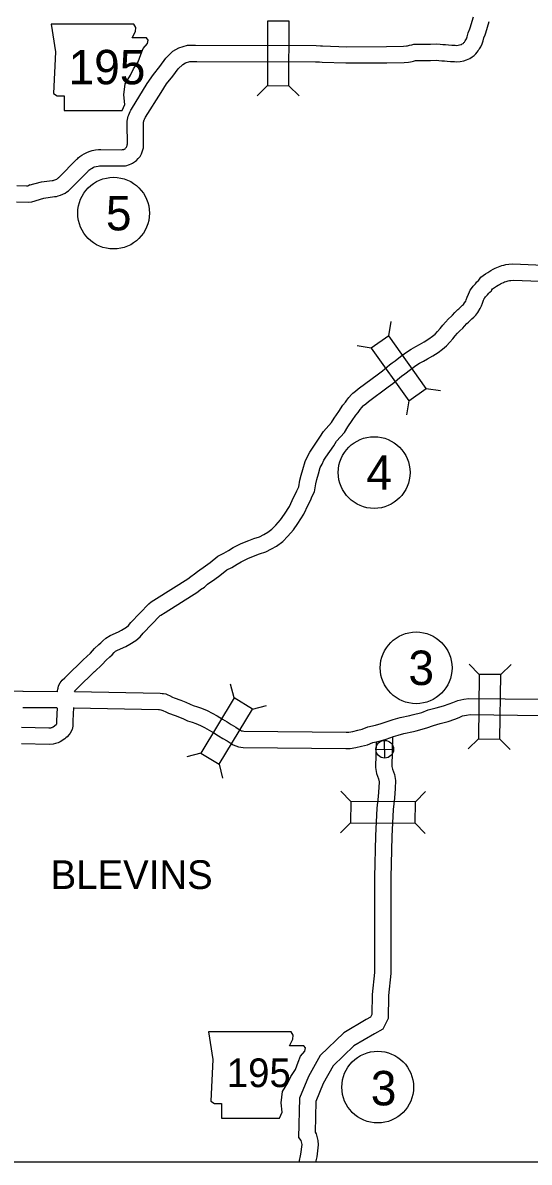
# Model space of a CAD drawing. Extents: x 79818 to 83933, y 50884 to 53307.
# Drawn here: x 81175.4 to 81299.7, y 52610.7 to 52890.4 of the extents above; entities that cross this region are included whole.
import ezdxf

# ---------------------------------------------------------------- set-up
doc = ezdxf.new("R2010")
doc.units = 0
for name, color, linetype in [('Level 10', 7, 'Continuous'), ('Level 12', 7, 'Continuous'), ('Level 15', 7, 'Continuous'), ('Level 20', 7, 'Continuous'), ('Level 21', 7, 'Continuous'), ('Level 26', 7, 'Continuous'), ('Level 27', 7, 'Continuous'), ('Level 6', 7, 'Continuous'), ('R_No Plot', 7, 'Continuous')]:
    doc.layers.add(name, color=color, linetype=linetype)

msp = doc.modelspace()

# ---------------------------------------------------------------- linework, layer by layer
at = {"layer": 'Level 10'}
for points in [[(81281, 52880.86), (81281.3, 52880.84), (81281.88, 52880.81), (81282.75, 52880.85), (81283.63, 52881.06), (81284.24, 52881.25), (81284.65, 52881.42), (81285.1, 52881.63), (81285.68, 52881.97), (81286.19, 52882.37), (81286.57, 52882.75), (81286.91, 52883.13), (81287.16, 52883.49), (81287.33, 52883.79), (81287.46, 52883.97), (81287.75, 52884.45), (81288.13, 52885.16), (81288.34, 52885.97), (81288.51, 52886.64), (81288.83, 52887.41), (81289, 52887.87), (81289.84, 52890.64)], [(81281.22, 52884.85), (81281.52, 52884.83), (81281.88, 52884.81), (81282.19, 52884.83), (81282.59, 52884.92), (81282.86, 52885.01), (81283.01, 52885.07), (81283.25, 52885.19), (81283.43, 52885.28), (81283.52, 52885.36), (81283.65, 52885.49), (81283.77, 52885.62), (81283.78, 52885.64), (81283.93, 52885.91), (81284.1, 52886.15), (81284.29, 52886.45), (81284.38, 52886.63), (81284.46, 52886.94), (81284.7, 52887.91), (81285.11, 52888.88), (81285.21, 52889.14), (81286.02, 52891.82)], [(81202.08, 52869.16), (81205.97, 52875.43), (81207.47, 52877.7), (81209.04, 52879.66), (81210.5, 52881.64), (81212.23, 52883.38), (81213.73, 52884.22), (81215.8, 52884.86), (81217.76, 52884.9)], [(81205.56, 52867.19), (81209.36, 52873.29), (81210.71, 52875.35), (81212.21, 52877.23), (81213.54, 52879.03), (81214.67, 52880.16), (81215.32, 52880.53), (81216.43, 52880.87), (81218.13, 52880.9)], [(81201.08, 52860.53), (81201.05, 52865.56), (81201.05, 52865.85), (81201.07, 52866.2), (81201.12, 52866.61), (81201.21, 52867.05), (81201.3, 52867.43), (81201.42, 52867.81), (81201.57, 52868.2), (81201.74, 52868.57), (81201.95, 52868.95), (81202.08, 52869.16)], [(81205.08, 52860.56), (81205.05, 52865.54), (81205.05, 52865.68), (81205.06, 52865.83), (81205.08, 52865.99), (81205.11, 52866.19), (81205.15, 52866.34), (81205.2, 52866.49), (81205.26, 52866.65), (81205.31, 52866.76), (81205.43, 52866.98), (81205.56, 52867.19)], [(81188.65, 52856.82), (81188.83, 52856.99), (81189.05, 52857.19), (81189.45, 52857.53), (81189.89, 52857.84), (81190.48, 52858.21), (81191.13, 52858.53), (81191.7, 52858.76), (81192.42, 52858.99), (81193.26, 52859.17), (81194, 52859.25), (81194.59, 52859.26), (81199.7, 52859.22), (81199.92, 52859.23), (81199.99, 52859.24), (81200.04, 52859.25), (81200.18, 52859.28), (81200.21, 52859.29), (81200.33, 52859.34), (81200.38, 52859.37), (81200.53, 52859.46), (81200.65, 52859.56), (81200.74, 52859.66), (81200.86, 52859.81), (81200.94, 52859.96), (81200.99, 52860.07), (81201.04, 52860.22), (81201.06, 52860.32), (81201.07, 52860.42), (81201.08, 52860.62)], [(81191.44, 52853.96), (81191.57, 52854.08), (81191.67, 52854.17), (81191.9, 52854.36), (81192.11, 52854.51), (81192.43, 52854.71), (81192.78, 52854.89), (81193.06, 52855), (81193.44, 52855.12), (81193.89, 52855.21), (81194.28, 52855.25), (81194.63, 52855.26), (81199.77, 52855.22), (81200.27, 52855.24), (81200.63, 52855.29), (81200.95, 52855.35), (81201.35, 52855.46), (81201.63, 52855.55), (81202, 52855.71), (81202.35, 52855.88), (81202.86, 52856.2), (81203.35, 52856.6), (81203.77, 52857.03), (81204.19, 52857.58), (81204.52, 52858.16), (81204.75, 52858.68), (81204.91, 52859.21), (81205.01, 52859.67), (81205.06, 52860.1), (81205.08, 52860.47)], [(81180.05, 52851.31), (81182.67, 52851.64), (81182.89, 52851.68), (81183.06, 52851.72), (81183.31, 52851.8), (81183.55, 52851.9), (81183.76, 52852.01), (81183.94, 52852.13), (81184.1, 52852.25), (81184.23, 52852.36), (81184.33, 52852.46), (81188.63, 52856.79)], [(81176.37, 52850.34), (81176.65, 52850.36), (81176.94, 52850.5), (81180.05, 52851.31)], [(81180.57, 52847.34), (81183.25, 52847.69), (81183.67, 52847.75), (81184.12, 52847.86), (81184.7, 52848.04), (81185.27, 52848.28), (81185.79, 52848.56), (81186.24, 52848.85), (81186.61, 52849.14), (81186.92, 52849.4), (81187.14, 52849.61), (81191.47, 52853.98)], [(81173.98, 52850.39), (81176.37, 52850.35)], [(81176.37, 52850.34), (81176.65, 52850.36), (81176.94, 52850.5), (81177.21, 52850.64)], [(81173.9, 52846.39), (81176.72, 52846.34)], [(81176.72, 52846.35), (81177.62, 52846.43), (81180.57, 52847.34)], [(81183.83, 52722.25), (81183.69, 52719.01), (81183.72, 52718.43), (81183.7, 52718.23), (81183.6, 52718.06), (81183.33, 52717.82), (81183.17, 52717.72), (81182.86, 52717.51), (81182.62, 52717.37), (81182.56, 52717.33), (81182.39, 52717.28), (81182.26, 52717.25), (81181.86, 52717.23), (81175.13, 52717.37)], [(81187.84, 52722.34), (81187.69, 52719.02), (81187.73, 52718.38), (81187.68, 52717.76), (81187.57, 52716.89), (81187.03, 52716), (81186.84, 52715.67), (81186.35, 52715.08), (81185.98, 52714.82), (81185.71, 52714.58), (81185.37, 52714.38), (81185.03, 52714.14), (81184.56, 52713.87), (81184.07, 52713.6), (81183.46, 52713.43), (81182.88, 52713.27), (81181.92, 52713.23), (81175.15, 52713.37)], [(81266.12, 52715.07), (81265.99, 52707.81), (81266.09, 52707.17), (81266.59, 52705.88), (81266.85, 52704.35), (81266.77, 52702.39), (81266.58, 52700.04), (81266.28, 52697.3), (81265.95, 52690.62), (81265.69, 52680.6), (81265.72, 52657.03), (81265.16, 52651.64), (81265.06, 52645.98), (81263.76, 52643.37), (81261.68, 52642.22), (81256.62, 52639.23), (81251.54, 52634.39), (81249.11, 52630.03), (81247.3, 52625.59), (81247.13, 52618.03), (81247.37, 52617.7), (81247.77, 52616.03), (81247.87, 52614.97), (81247.53, 52612.04), (81247.24, 52610.7)], [(81262.1, 52713.9), (81261.99, 52707.54), (81262.21, 52706.13), (81262.71, 52704.82), (81262.84, 52704.09), (81262.78, 52702.63), (81262.6, 52700.42), (81262.29, 52697.62), (81261.96, 52690.77), (81261.69, 52680.65), (81261.72, 52657.24), (81261.16, 52651.88), (81261.08, 52646.96), (81260.74, 52646.27), (81259.69, 52645.69), (81254.19, 52642.44), (81248.34, 52636.87), (81245.49, 52631.77), (81243.32, 52626.42), (81243.1, 52616.78), (81243.66, 52615.99), (81243.81, 52615.37), (81243.85, 52615.01), (81243.58, 52612.69), (81243.15, 52610.7)]]:
    msp.add_lwpolyline(points, dxfattribs=at)
at = {"layer": 'Level 12'}
for points in [[(81217.76, 52884.9), (81247.4, 52884.81), (81248.5, 52884.73), (81248.96, 52884.69), (81254.94, 52884.5), (81264.63, 52884.52)], [(81264.63, 52884.52), (81268.81, 52884.64), (81269.59, 52884.7), (81269.79, 52884.73), (81270.05, 52884.79), (81270.32, 52884.86), (81270.88, 52884.99), (81271.32, 52885.08), (81272.16, 52885.14), (81273.02, 52885.14), (81273.69, 52885.14), (81274.31, 52885.14), (81275.47, 52885.12), (81277.01, 52885.16), (81277.82, 52885.1), (81278.48, 52885.04), (81279.12, 52885.01), (81279.87, 52884.96), (81280.68, 52884.88), (81281.22, 52884.85)], [(81218.13, 52880.9), (81247.24, 52880.81), (81248.2, 52880.74), (81248.86, 52880.69), (81254.66, 52880.5), (81264.75, 52880.52)], [(81264.75, 52880.52), (81269.02, 52880.64), (81270.08, 52880.73), (81270.52, 52880.8), (81270.95, 52880.89), (81271.3, 52880.98), (81271.75, 52881.09), (81271.85, 52881.11), (81272.3, 52881.14), (81273.04, 52881.14), (81273.7, 52881.14), (81274.28, 52881.14), (81275.48, 52881.12), (81276.91, 52881.15), (81277.49, 52881.11), (81278.22, 52881.04), (81278.9, 52881.02), (81279.53, 52880.97), (81280.38, 52880.89), (81281, 52880.86)]]:
    msp.add_lwpolyline(points, dxfattribs=at)
at = {"layer": 'Level 15'}
for points in [[(81287.11, 52826.94), (81287.81, 52827.94), (81288.95, 52828.74), (81289.48, 52829.06), (81289.79, 52829.27), (81290.28, 52829.59), (81290.8, 52829.87), (81291.29, 52830.11), (81291.7, 52830.28), (81292.15, 52830.5), (81292.98, 52830.75), (81293.44, 52830.86), (81293.92, 52831), (81294.67, 52831.12), (81295.65, 52831.2), (81308.86, 52830.66)], [(81190.28, 52734), (81192.05, 52735.67), (81193.06, 52736.77), (81194.1, 52737.75), (81194.58, 52738.16), (81195.04, 52738.64), (81195.77, 52739.35), (81196.83, 52739.96), (81198.89, 52740.88), (81199.63, 52741.3), (81200.84, 52742.05), (81201.36, 52742.47), (81201.91, 52743.2), (81206.38, 52747.74), (81206.9, 52748.21), (81208.23, 52749.03), (81215.94, 52753.88), (81216.64, 52754.49), (81217.58, 52755.08), (81218.28, 52755.7), (81220.24, 52757.1), (81221.4, 52757.91), (81223.29, 52759.41), (81224.71, 52760.18), (81225.9, 52760.87), (81227.02, 52761.59), (81229.01, 52762.52), (81230.87, 52763.27), (81232.12, 52763.81), (81233.51, 52764.23), (81234.55, 52764.76), (81235.52, 52765.3), (81236.56, 52766.08), (81237.53, 52767.06), (81238.64, 52768.37), (81239.63, 52769.76), (81240.86, 52771.63), (81241.82, 52773.85), (81242.45, 52774.94), (81242.65, 52775.52), (81243.11, 52776.47), (81243.37, 52778.09), (81243.75, 52779.34), (81244.11, 52780.69), (81244.66, 52782.69), (81245.26, 52783.87), (81245.82, 52784.98), (81246.46, 52785.96), (81247.5, 52787.43), (81248.33, 52788.67), (81249.19, 52790.07), (81251.12, 52792.24), (81251.83, 52793.35), (81252.92, 52794.99), (81253.95, 52796.52), (81254.59, 52797.26), (81254.95, 52797.75), (81255.42, 52798.43), (81256.03, 52799.12), (81256.42, 52799.48), (81257.03, 52799.93), (81257.67, 52800.52), (81262.65, 52804.18), (81263.69, 52804.97), (81265.38, 52806.4), (81266.07, 52806.87), (81266.76, 52807.37), (81268.08, 52808.42), (81269.58, 52809.55), (81270.72, 52810.26), (81271.81, 52810.87), (81272.78, 52811.36), (81273.93, 52812.04), (81275.07, 52812.79), (81275.97, 52813.41), (81276.61, 52813.96), (81277.16, 52814.56), (81277.79, 52815.34), (81278.45, 52816.14), (81279.13, 52816.91), (81279.9, 52817.68), (81280.62, 52818.35), (81280.85, 52818.56), (81281.42, 52819.28), (81282.15, 52819.99), (81282.38, 52820.16), (81282.85, 52820.63), (81283.3, 52821.02), (81283.51, 52821.24), (81283.8, 52821.6), (81284.08, 52822.05), (81284.2, 52822.34), (81284.43, 52822.98), (81284.73, 52823.78), (81284.98, 52824.32), (81285.17, 52824.72), (81285.48, 52825.18), (81285.88, 52825.73), (81286.45, 52826.31), (81286.85, 52826.77), (81287.08, 52826.98)], [(81290.37, 52824.63), (81290.68, 52825.06), (81291.15, 52825.39), (81291.63, 52825.69), (81292.01, 52825.94), (81292.33, 52826.15), (81292.63, 52826.31), (81292.94, 52826.47), (81293.33, 52826.62), (81293.61, 52826.76), (81294.03, 52826.89), (81294.48, 52827), (81294.8, 52827.09), (81295.15, 52827.14), (81295.74, 52827.2), (81308.77, 52826.66)], [(81193.02, 52731.09), (81194.9, 52732.86), (81195.91, 52733.96), (81196.76, 52734.77), (81197.33, 52735.24), (81197.88, 52735.83), (81198.2, 52736.13), (81198.64, 52736.39), (81200.69, 52737.31), (81201.66, 52737.85), (81203.15, 52738.78), (81204.26, 52739.67), (81204.94, 52740.58), (81209.16, 52744.86), (81209.32, 52745), (81210.34, 52745.63), (81218.35, 52750.66), (81219.04, 52751.28), (81219.97, 52751.86), (81220.77, 52752.56), (81222.55, 52753.83), (81223.8, 52754.7), (81225.5, 52756.06), (81226.67, 52756.69), (81227.99, 52757.46), (81228.96, 52758.08), (81230.6, 52758.85), (81232.4, 52759.58), (81233.5, 52760.05), (81235.02, 52760.51), (81236.42, 52761.23), (81237.7, 52761.93), (81239.2, 52763.07), (81240.48, 52764.36), (81241.8, 52765.91), (81242.93, 52767.49), (81244.39, 52769.72), (81245.4, 52772.04), (81246.1, 52773.26), (81246.36, 52773.99), (81246.97, 52775.26), (81247.28, 52777.19), (81247.6, 52778.25), (81247.97, 52779.65), (81248.41, 52781.23), (81248.83, 52782.06), (81249.29, 52782.98), (81249.77, 52783.71), (81250.79, 52785.16), (81251.7, 52786.51), (81252.42, 52787.68), (81254.32, 52789.82), (81255.18, 52791.17), (81256.24, 52792.77), (81257.13, 52794.09), (81257.71, 52794.75), (81258.2, 52795.41), (81258.58, 52795.96), (81258.91, 52796.34), (81258.98, 52796.4), (81259.57, 52796.83), (81260.21, 52797.42), (81265.04, 52800.98), (81266.19, 52801.84), (81267.82, 52803.22), (81268.37, 52803.6), (81269.17, 52804.18), (81270.53, 52805.26), (81271.84, 52806.25), (81272.75, 52806.81), (81273.69, 52807.33), (81274.71, 52807.86), (81276.04, 52808.64), (81277.31, 52809.47), (81278.41, 52810.24), (81279.4, 52811.08), (81280.19, 52811.95), (81280.89, 52812.81), (81281.5, 52813.55), (81282.05, 52814.17), (81282.67, 52814.79), (81283.36, 52815.44), (81283.81, 52815.86), (81284.39, 52816.59), (81284.73, 52816.92), (81284.98, 52817.1), (81285.57, 52817.7), (81286.09, 52818.14), (81286.55, 52818.64), (81287.07, 52819.29), (81287.64, 52820.21), (81287.93, 52820.89), (81288.18, 52821.58), (81288.43, 52822.25), (81288.59, 52822.62), (81288.64, 52822.7), (81288.76, 52822.89), (81288.94, 52823.14), (81289.39, 52823.6), (81289.72, 52823.97), (81290.09, 52824.31)], [(81290.03, 52824.26), (81290.41, 52824.58)], [(81183.89, 52726.15), (81183.88, 52726.19), (81184.07, 52727.05), (81184.18, 52727.61), (81184.61, 52728.34), (81185.12, 52729), (81185.72, 52729.58), (81186.13, 52730), (81190.26, 52733.98)], [(81162.05, 52733.72), (81165.37, 52731.15), (81166.18, 52730.29), (81166.65, 52729.71), (81167.29, 52729.11), (81168.08, 52728.14), (81168.5, 52727.54), (81168.87, 52727.01), (81168.98, 52726.9), (81169.15, 52726.76), (81169.33, 52726.64), (81169.38, 52726.62), (81169.82, 52726.49), (81170.4, 52726.41), (81175.5, 52726.31)], [(81188.02, 52726.21), (81188.11, 52726.33), (81188.54, 52726.74), (81188.95, 52727.16), (81193.04, 52731.1)], [(81175.47, 52726.31), (81184.05, 52726.27)], [(81188.13, 52726.22), (81209.17, 52725.84), (81209.62, 52725.75), (81209.93, 52725.71), (81210.54, 52725.63), (81210.98, 52725.4), (81211.42, 52725.24), (81212.15, 52724.85), (81212.56, 52724.69), (81214.23, 52724.08), (81215.4, 52723.63), (81216.45, 52723.16), (81217.23, 52722.82), (81218.29, 52722.49), (81219.3, 52722.12), (81220.7, 52721.55), (81221.88, 52720.94), (81223.15, 52720.25), (81224.41, 52719.48), (81225.54, 52718.77), (81226.56, 52718.16), (81227.69, 52717.49), (81228.52, 52716.92), (81228.86, 52716.7), (81229.12, 52716.61), (81229.29, 52716.54), (81229.69, 52716.5), (81254.74, 52716.28), (81255.38, 52716.26), (81256.37, 52716.45), (81257.63, 52716.7), (81258.71, 52716.98), (81260.07, 52717.53), (81261.92, 52717.97), (81263.38, 52718.34), (81265.04, 52718.93), (81266.29, 52719.37), (81268, 52719.83), (81270.37, 52720.34), (81270.92, 52720.47), (81273.3, 52721.11), (81274.89, 52721.72), (81276.81, 52722.25), (81278.63, 52722.7), (81280.04, 52723.2), (81280.96, 52723.54), (81282.11, 52724.06), (81283.61, 52724.35), (81284.86, 52724.55), (81302.68, 52724.34)], [(81175.45, 52722.31), (81183.77, 52722.27)], [(81187.85, 52722.23), (81208.75, 52721.85), (81208.97, 52721.8), (81209.27, 52721.76), (81209.79, 52721.57), (81210.49, 52721.2), (81211.17, 52720.94), (81212.82, 52720.33), (81213.87, 52719.93), (81214.83, 52719.5), (81215.82, 52719.07), (81217.01, 52718.7), (81217.87, 52718.39), (81219.02, 52717.92), (81220.01, 52717.4), (81221.15, 52716.78), (81222.31, 52716.08), (81223.44, 52715.37), (81224.51, 52714.72), (81225.55, 52714.11), (81226.31, 52713.59), (81227.06, 52713.1), (81227.72, 52712.86), (81228.38, 52712.61), (81229.47, 52712.51), (81254.67, 52712.28), (81255.71, 52712.25), (81257.14, 52712.52), (81258.52, 52712.8), (81259.96, 52713.17), (81261.29, 52713.71), (81262.87, 52714.08), (81264.55, 52714.51), (81266.37, 52715.16), (81267.48, 52715.54), (81268.94, 52715.94), (81271.25, 52716.44), (81271.9, 52716.59), (81274.54, 52717.3), (81276.14, 52717.91), (81277.83, 52718.38), (81279.79, 52718.87), (81281.41, 52719.44), (81282.48, 52719.84), (81283.33, 52720.22), (81284.31, 52720.41), (81285.16, 52720.55), (81302.62, 52720.34)]]:
    msp.add_lwpolyline(points, dxfattribs=at)
at = {"layer": 'Level 20'}
for p, q in [((81235.45, 52874.93), (81232.95, 52872.44)), ((81240.73, 52874.91), (81243.21, 52872.42)), ((81265.21, 52813.54), (81265.79, 52817.01)), ((81260.91, 52810.47), (81257.44, 52811.05)), ((81274.41, 52800.64), (81277.89, 52800.07)), ((81270.12, 52797.58), (81269.54, 52794.1)), ((81287.4, 52730.44), (81284.94, 52732.96)), ((81292.68, 52730.38), (81295.2, 52732.84)), ((81227.25, 52724.65), (81226.4, 52728.07)), ((81231.77, 52721.93), (81235.19, 52722.78)), ((81287.21, 52714.6), (81284.69, 52712.15)), ((81292.49, 52714.54), (81294.95, 52712.02)), ((81219.08, 52711.08), (81215.66, 52710.23)), ((81223.6, 52708.36), (81224.45, 52704.94)), ((81255.89, 52699.27), (81253.42, 52701.77)), ((81271.73, 52699.17), (81274.24, 52701.65)), ((81255.86, 52693.99), (81253.36, 52691.51)), ((81271.7, 52693.89), (81274.17, 52691.39))]:
    msp.add_line(p, q, dxfattribs=at)
for points in [[(81235.49, 52890.77), (81235.45, 52874.93), (81240.73, 52874.91), (81240.77, 52890.75)], [(81260.91, 52810.47), (81270.12, 52797.58), (81274.41, 52800.64), (81265.21, 52813.54)], [(81292.49, 52714.54), (81292.68, 52730.38), (81287.4, 52730.44), (81287.21, 52714.6)], [(81227.25, 52724.65), (81219.08, 52711.08), (81223.6, 52708.36), (81231.77, 52721.93)], [(81255.86, 52693.99), (81271.7, 52693.89), (81271.73, 52699.17), (81255.89, 52699.27)]]:
    msp.add_lwpolyline(points, close=True, dxfattribs=at)
at = {"layer": 'Level 21'}
for points in [[(81182.42, 52890.02), (81183.44, 52883.25), (81182.98, 52872.98), (81183.89, 52872.42), (81185.58, 52872.42), (81185.58, 52868.81), (81199.79, 52868.81), (81200.47, 52870.28), (81200.24, 52872.65), (81200.58, 52875.35), (81201.82, 52877.5), (81202.61, 52879.08), (81203.74, 52880.77), (81204.41, 52882.57), (81204.98, 52884.04), (81205.99, 52885.28), (81206.22, 52886.07), (81205.77, 52886.63), (81202.27, 52886.63), (81203.06, 52888.21), (81203.17, 52889.23), (81202.71, 52890.01)], [(81221.01, 52642.68), (81222.03, 52635.91), (81221.58, 52625.65), (81222.48, 52625.09), (81224.17, 52625.09), (81224.17, 52621.48), (81238.38, 52621.48), (81239.06, 52622.94), (81238.83, 52625.31), (81239.17, 52628.02), (81240.41, 52630.16), (81241.2, 52631.74), (81242.33, 52633.43), (81243.01, 52635.24), (81243.57, 52636.7), (81244.59, 52637.94), (81244.81, 52638.73), (81244.36, 52639.3), (81240.86, 52639.3), (81241.65, 52640.88), (81241.77, 52641.89), (81241.3, 52642.67)]]:
    msp.add_lwpolyline(points, close=True, dxfattribs=at)
at = {"layer": 'Level 26'}
for p, q in [((81262.04, 52712.01), (81266.38, 52712.11)), ((81264.26, 52709.89), (81264.16, 52714.23))]:
    msp.add_line(p, q, dxfattribs=at)
msp.add_circle((81264.21, 52712.06), 2.17, dxfattribs=at)
at = {"layer": 'Level 27'}
for centre in [(81197.71, 52843.64), (81261.62, 52779.97), (81271.92, 52732.04), (81262.49, 52629.13)]:
    msp.add_circle(centre, 8.8, dxfattribs=at)
at = {"layer": 'R_No Plot'}
msp.add_lwpolyline([(80798.6, 53193.52), (81459.98, 53193.52), (81459.98, 52610.7), (80798.6, 52610.7)], close=True, dxfattribs=at)
msp.add_lwpolyline([(80798.6, 53193.52), (81459.98, 53193.52), (81459.98, 52610.7), (80798.6, 52610.7)], close=True, dxfattribs=at)

# ---------------------------------------------------------------- texts
at = {"layer": 'Level 21'}
for height, p in [(8.448, (81186.66, 52875.27)), (7.04, (81225.47, 52629.13))]:
    msp.add_text('195', height=height, dxfattribs=at).set_placement(p)
at = {"layer": 'Level 27'}
for s, p in [('5', (81195.82, 52839.41)), ('4', (81259.73, 52775.74)), ('3', (81270.03, 52727.82)), ('3', (81260.8, 52624.65))]:
    msp.add_text(s, height=8.45, dxfattribs=at).set_placement(p)
at = {"layer": 'Level 6'}
msp.add_text('BLEVINS', height=7.04, dxfattribs=at).set_placement((81182.25, 52677.76))

doc.saveas('drawing.dxf')
